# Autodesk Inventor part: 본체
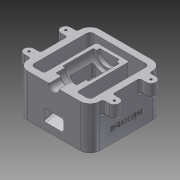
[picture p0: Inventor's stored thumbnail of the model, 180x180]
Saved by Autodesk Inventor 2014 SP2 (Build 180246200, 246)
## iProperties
Created: 2018-01
Part Number: 본체
Material: 알루미늄 6061
Document SubType Name: Modeling
Designer: 거성
Density: 2.71 g/cm^3
Appearance: 알루미늄 - 평지
Mass: 1031.84 g
Surface Area: 853.24 cm^2
Volume: 380.754 cm^3
Author: 거성
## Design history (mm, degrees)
sketch "스케치1"
  geometry: L1 (55, 55)-(-55, 55); L2 (-55, 55)-(-55, -55); L3 (-55, -55)-(55, -55); L4 (55, -55)-(55, 55); L5 (45, 45)-(-45, 45); L6 (-45, 45)-(-45, -45); L7 (-45, -45)-(45, -45); L8 (45, -45)-(45, 45); 5 further points
  constraints: 16 end point, 4 midpoint, 4 parallel, 2 horizontal, 2 horizontal alignment, 2 perpendicular, 2 vertical alignment
  dimensions: "d0" = 110 distance of L1.end L2.end; "d1" = 110 distance of L2.end L3.end; "d2" = 10 distance between parallel lines of L3 L7; "d3" = 10 distance between parallel lines of L4 L8
extrude "돌출1" new body sketch "스케치1" distance "d4" = 65; taper "d5" = 0 deg
sketch "스케치2"
  geometry: L1 (0, 0)-(110, 0) reference; L2 (0, 0)-(0, 65) reference; 2 further points
  constraints: 1 other
  dimensions: "d6" = 55 distance from line of point (55, 20) L2; "d7" = 20 distance from line of point (55, 20) L1
feature "엠보싱1" sketch "스케치2" dims "d8" = 0.5, "d9" = 0
sketch "스케치3"
  geometry: L1 (-55, -55)-(55, -55) reference; L2 (-55, 55)-(-55, -55) reference; L3 (-65, -35.5)-(-55, -35.5); L4 (-65, -20.5)-(-55, -20.5); L5 (-55, -20.5)-(-55, -35.5); A1 r 7.5 centre (-65, -28) between (-65, -35.5) and (-65, -20.5); 1 further point
  constraints: 6 end point, 2 perpendicular, 2 point on circle, 2 point on line, 2 tangent, 1 centre point, 1 collinear
  dimensions: "d10" = 7.5 radius of A1; "d11" = 27 distance from line of A1.centre L1; "d12" = 10 distance from line of A1.centre L2
extrude "돌출2" join sketch "스케치3" distance "d13" = 20; taper "d14" = 0 deg
sketch "스케치4"
  geometry: A1 r 7.5 centre (-65, -28) between (-65, -20.5) and (-65, -35.5) reference; 2 further points
  constraints: 1 coincident
hole "구멍1" sketch "스케치4" at (-65, -28) diameter "d15" = 3.242; stored, may be unused: countersink angle "d19" = 90 deg, drill point angle "d21" = 118 deg; dims "d16" = 9, "d17" = 4, "d18" = 2, "d20" = 11
node "작업 평면1"
sketch "스케치5"
  geometry: L1 (0, 45)-(65, 45) reference; L2 (8.564, 45)-(30, -35); L3 (65, 45)-(65, -45) reference; L4 (30, -35)-(65, -35); L5 (0, -45)-(0, 45) reference; L6 (0, -55)-(65, -55) reference; 1 further point
  constraints: 4 end point, 2 point on line, 1 perpendicular
  dimensions: "d26" = 105 deg angle of L1 L2; "d27" = 30 distance from line of L2.end L5; "d28" = 20 distance between parallel lines of L4 L6
extrude "돌출3" join sketch "스케치5" stored distance "d29" = 50; taper "d30" = 0 deg
node "작업 평면2"
sketch "스케치6"
  geometry: L1 (65, 45)-(65, -35) reference; L2 (65, 55)-(65, -35); L3 (57.5, 55)-(57.5, 36); L4 (57.5, 36)-(49, 36); L5 (49, 36)-(49, 22); L6 (49, 22)-(45, 22); L7 (45, 22)-(45, -25); L8 (45, -25)-(50, -25); L9 (50, -25)-(50, -30); L10 (50, -30)-(65, -30); L11 (0, 55)-(65, 55) reference; L12 (57.5, 55)-(65, 55); 2 further points
  constraints: 20 end point, 6 parallel, 2 collinear, 2 perpendicular, 1 horizontal alignment, 1 midpoint, 1 point on line
  dimensions: "d32" = 15 diameter of L3 L2; "d33" = 32 diameter of L5 L2; "d34" = 40 diameter of L7 L2; "d35" = 30 diameter of L9 L2; "d36" = 19 distance between parallel lines of L4 L11; "d37" = 14 distance between parallel lines of L6 L4; "d38" = 47 distance between parallel lines of L8 L6; "d39" = 5 distance between parallel lines of L10 L8
revolve "회전1" sketch "스케치6" stored, may be unused: angle "d40" = 90 deg
node "작업 평면3"
sketch "스케치7"
  geometry: L1 (0, 55)-(65, 55) reference; L2 (45, 22)-(45, -25) reference; L3 (30, -35)-(8.564, 45) reference; L4 (11.061, 55)-(31.157, -20); L5 (31.157, -20)-(45, -20); L6 (45, 17)-(39.243, 17); L7 (39.243, 17)-(29.061, 55); L8 (45, 22)-(65, 22) reference; L9 (45, 17)-(45, -20); L10 (45, 17)-(68, 17); L11 (68, 17)-(68, -20); L12 (68, -20)-(45, -20); 1 further point
  constraints: 16 end point, 4 point on line, 3 perpendicular, 2 collinear, 2 parallel
  dimensions: "d42" = 5 distance from line of L3.end L4; "d45" = 75 deg angle of L1 L7; "d46" = 18 distance of L7.end L4.start; "d64" = 5 distance between parallel lines of L6 L8; "d65" = 37 distance between parallel lines of L5 L6; "d66" = 23 distance between parallel lines of L11 L9
extrude "돌출4" cut sketch "스케치7" stored distance "d49" = 30; taper "d50" = 0 deg
chamfer "모따기1" distance "d51" = 1; stored, may be unused: second distance "d52" = 2, angle "d53" = 45 deg
fillet "모깎기1" dims "d54" = 15, "d55" = 5, "d56" = 3, "d57" = 1, "d58" = 3
fillet "모깎기2" dims "d59" = 3, "d60" = 3
fillet "모깎기3" dims "d67" = 3
fillet "모깎기4" dims "d68" = 3
node "솔리드1"
pattern_linear "직사각형 패턴1" dims "d24" = 56
mirror "대칭1"
other parameters: "d25" = 0, "d31" = 0, "d41" = 0
